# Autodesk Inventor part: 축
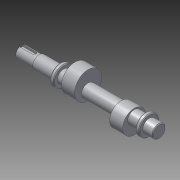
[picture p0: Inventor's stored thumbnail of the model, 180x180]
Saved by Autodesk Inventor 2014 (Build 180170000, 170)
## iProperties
Created: 2014-12
Part Number: 축
Material: 알루미늄 6061
Document SubType Name: Modeling
Designer: Owner
Density: 2.71 g/cm^3
Appearance: 알루미늄 - 평지
Mass: 170.354 g
Surface Area: 153.402 cm^2
Volume: 62.8614 cm^3
Author: Owner
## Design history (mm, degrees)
sketch "스케치1"
  geometry: L1 (90, 0)-(-90, 0); L2 (90, 0)-(90, 7.5); L3 (90, 7.5)-(66, 7.5); L4 (66, 7.5)-(66, 8.5); L5 (66, 8.5)-(39, 8.5); L6 (39, 8.5)-(39, 13); L7 (39, 13)-(34, 13); L8 (34, 13)-(34, 8.5); L9 (34, 8.5)-(-72, 8.5); L10 (-72, 8.5)-(-72, 13); L11 (-72, 13)-(-77, 13); L12 (-77, 13)-(-77, 8.5); L13 (-77, 8.5)-(-90, 8.5); L14 (-90, 8.5)-(-90, 0); 4 further points
  constraints: 28 end point, 11 parallel, 3 midpoint, 2 perpendicular, 1 coincident, 1 horizontal, 1 horizontal alignment
  dimensions: "d0" = 180 distance of L1.start L1.end; "d1" = 15 diameter of L3 L1; "d2" = 17 diameter of L4.end L1; "d3" = 26 diameter of L6.end L1; "d4" = 17 diameter of L13.end L1; "d5" = 26 diameter of L11 L1; "d6" = 24 distance of L2.end L3.end; "d7" = 27 distance of L4.end L5.end; "d8" = 5 distance of L6.end L7.end; "d9" = 13 distance of L12.end L13.end; "d10" = 5 distance of L10.end L11.end
revolve "회전1" sketch "스케치1" stored, may be unused: angle "d11" = 90 deg
node "작업 평면1"
sketch "스케치2"
  geometry: C1 r 17.5 at (-6, 0); C2 r 8.5 at (0, 0) reference; 1 further point
  constraints: 1 centre point, 1 horizontal alignment
  dimensions: "d13" = 35 diameter of C1; "d14" = 6 distance of point (0, 0) C1.centre
extrude "돌출1" join sketch "스케치2" distance "d15" = 17; taper "d16" = 0 deg
node "작업 평면2"
sketch "스케치3"
  geometry: C1 r 15 at (-5, 0); 1 further point
  constraints: 1 centre point, 1 horizontal alignment
  dimensions: "d18" = 30 diameter of C1; "d19" = 5 distance of C1.centre point (0, 0)
extrude "돌출2" join sketch "스케치3" distance "d20" = 17; taper "d21" = 0 deg
node "작업 평면3"
sketch "스케치4"
  geometry: L1 (-12.987, 0)-(5.5, 0); L2 (-12, -2.5)-(5.5, -2.5); L3 (5.5, 2.5)-(-12, 2.5); L4 (-12, 7.5)-(-12, -7.5) reference; A1 r 2.5 centre (5.5, 0) between (5.5, -2.5) and (5.5, 2.5); 3 further points
  constraints: 8 end point, 2 midpoint, 2 parallel, 2 point on circle, 2 point on line, 2 tangent, 1 centre point, 1 horizontal, 1 horizontal alignment
  dimensions: "d22" = 20 dimension on A1 L4; "d23" = 5 distance between parallel lines of L2 L3
extrude "돌출3" cut sketch "스케치4" distance "d24" = 3; taper "d25" = 0 deg
chamfer "모따기1" distance "d26" = 1; stored, may be unused: second distance "d27" = 2, angle "d28" = 45 deg
node "솔리드1"
other parameters: "d12" = 14.5, "d17" = 14.5
